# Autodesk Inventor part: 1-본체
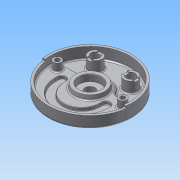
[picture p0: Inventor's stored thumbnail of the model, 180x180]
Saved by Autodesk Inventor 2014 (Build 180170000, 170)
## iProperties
Created: 2015-06
Part Number: 1-본체
Material: 알루미늄 6061
Document SubType Name: Modeling
Designer: Administrator
Density: 2.71 g/cm^3
Appearance: 알루미늄 - 평지
Mass: 1074.13 g
Surface Area: 1042.86 cm^2
Volume: 396.358 cm^3
Author: Administrator
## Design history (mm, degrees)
sketch "스케치1"
  geometry: C1 r 95 at (0, 0); 1 further point
  constraints: 1 centre point, 1 coincident
  dimensions: "d0" = 190 diameter of C1
extrude "돌출1" new body sketch "스케치1" distance "d1" = 32; taper "d2" = 0 deg
feature "쉘1" dims "d3" = 14, "d4" = 5
sketch "스케치2"
  geometry: L1 (0, 0)-(-94.075, -13.221); L2 (0, 0)-(94.075, -13.221); C1 r 90 at (0, 0) reference; A1 r 95 centre (0, 0) between (-94.075, -13.221) and (94.075, -13.221); 1 further point
  constraints: 4 end point, 3 point on circle, 1 centre point, 1 coincident, 1 vertical alignment, 2 other
  dimensions: "d5" = 164 deg angle of L2 L1
extrude "돌출2" cut sketch "스케치2" distance "d6" = 5; taper "d7" = 0 deg
sketch "스케치3"
  geometry: C1 r 90 at (0, 0) reference; C2 r 35 at (0, 0)
  constraints: 1 centre point, 1 coincident
  dimensions: "d8" = 70 diameter of C2
extrude "돌출3" join sketch "스케치3" distance "d9" = 10; taper "d10" = -10 deg
sketch "스케치4"
  geometry: C1 r 95 at (0, 0) reference; C2 r 26 at (0, 0)
  constraints: 1 centre point, 1 coincident
  dimensions: "d11" = 52 diameter of C2
extrude "돌출4" join sketch "스케치4" distance "d12" = 12; taper "d13" = -15 deg
hole "구멍1" diameter "d16" = 23; stored, may be unused: countersink angle "d20" = 90 deg, drill point angle "d22" = 118 deg; dims "d14" = 10, "d15" = 10, "d17" = 6, "d18" = 50, "d19" = 15, "d21" = 8
sketch "스케치5"
  geometry: L1 (-75.657, 16)-(-45.033, 16); L2 (45.033, 16)-(75.657, 16); C1 r 35 at (0, 0) reference; A1 r 90 centre (0, 0) between (-88.566, 16) and (88.566, 16) reference; A2 r 42 centre (0, 0) between (36.373, 21) and (-36.373, 21); A3 r 10 centre (-45.033, 26) between (-45.033, 16) and (-36.373, 21); A4 r 10 centre (45.033, 26) between (36.373, 21) and (45.033, 16); A5 r 90 centre (0, 0) between (85.114, 29.25) and (-85.114, 29.25); A6 r 10 centre (-75.657, 26) between (-85.114, 29.25) and (-75.657, 16); A7 r 10 centre (75.657, 26) between (75.657, 16) and (85.114, 29.25); 2 further points
  constraints: 19 point on circle, 8 tangent, 6 centre point, 4 end point, 4 point on line, 2 coincident, 2 equal radius, 2 horizontal, 1 collinear
  dimensions: "d23" = 42 radius of A2; "d24" = 16 distance from line of C1.centre L1; "d63" = 10 radius of A3; "d64" = 10 radius of A6
extrude "돌출5" cut sketch "스케치5" distance "d25" = 7; taper "d26" = 0 deg
sketch "스케치6"
  geometry: C1 r 15 at (-40, 52); C2 r 15 at (40, 52); A1 r 42 centre (0, 0) between (36.373, 21) and (-36.373, 21) reference; 2 further points
  constraints: 2 centre point, 1 equal radius, 1 horizontal alignment
  dimensions: "d27" = 80 distance of C2.centre C1.centre; "d28" = 52 vertical distance of A1.centre C1.centre; "d29" = 40 horizontal distance of A1.centre C1.centre; "d30" = 30 diameter of C1
extrude "돌출6" join sketch "스케치6" stored distance "d31" = 12; taper "d32" = 0 deg
sketch "스케치7"
  geometry: C1 r 15 at (0, 0) reference; C2 r 15 at (80, 0) reference; C3 r 10 at (0, 0); C4 r 10 at (80, 0); 1 further point
  constraints: 2 centre point, 2 coincident, 1 equal radius
  dimensions: "d33" = 20 diameter of C3
extrude "돌출7" cut sketch "스케치7" stored distance "d34" = 12; taper "d35" = 0 deg
sketch "스케치8"
  geometry: C1 r 9 at (-74, 0); C2 r 9 at (74, 0); A1 r 90 centre (0, 0) between (-85.114, 29.25) and (85.114, 29.25) reference; 2 further points
  constraints: 2 centre point, 2 horizontal alignment, 1 equal radius
  dimensions: "d36" = 148 distance of C2.centre C1.centre; "d37" = 74 distance of A1.centre C1.centre; "d38" = 18 diameter of C1
extrude "돌출8" join sketch "스케치8" stored distance "d39" = 12; taper "d40" = 0 deg
sketch "스케치9"
  geometry: L1 (75.657, 16)-(45.033, 16) reference; L2 (-59, -14)-(-59, -19); L3 (-41, -14)-(-41, -19); L4 (41, -14)-(41, -19); L5 (59, -14)-(59, -19); A1 r 90 centre (0, 0) between (-85.114, 29.25) and (85.114, 29.25) reference; A2 r 59 centre (0, -19) between (-59, -19) and (59, -19); A3 r 41 centre (0, -19) between (-41, -19) and (41, -19); A4 r 9 centre (-50, -14) between (-59, -14) and (-41, -14); A5 r 9 centre (50, -14) between (41, -14) and (59, -14); 3 further points
  constraints: 12 point on circle, 8 end point, 6 tangent, 4 centre point, 3 horizontal alignment, 3 parallel, 1 equal radius, 1 perpendicular, 1 vertical alignment
  dimensions: "d41" = 59 radius of A2; "d42" = 19 distance of A2.centre A1.centre; "d43" = 41 radius of A3; "d44" = 18 diameter of A4; "d45" = 5 vertical distance of A2.end A5.centre
extrude "돌출9" cut sketch "스케치9" distance "d46" = 7; taper "d47" = 0 deg
sketch "스케치10"
  geometry: L1 (-6, 13.748)-(-6, -13.748); L2 (6, 13.748)-(6, -13.748); L3 (66.252, 6)-(93.748, 6); L4 (66.252, -6)-(93.748, -6); A1 r 15 centre (0, 0) between (-6, 13.748) and (-6, -13.748) reference; A2 r 15 centre (80, 0) between (66.252, 6) and (93.748, 6) reference; 1 further point
  constraints: 8 end point, 8 point on circle, 3 parallel, 1 perpendicular, 1 vertical
  dimensions: "d48" = 12 distance between parallel lines of L2 L1; "d49" = 12 distance between parallel lines of L4 L3
extrude "돌출10" cut sketch "스케치10" distance "d50" = 3; taper "d51" = 0 deg
sketch "스케치11"
  geometry: C1 r 9 at (74, 0) reference; C2 r 9 at (-74, 0) reference; 2 further points
  constraints: 2 coincident
hole "구멍2" sketch "스케치11" at (-74, 0), (74, 0) diameter "d52" = 11; stored, may be unused: countersink angle "d56" = 90 deg, drill point angle "d58" = 118 deg; dims "d53" = 6, "d54" = 18, "d55" = 11, "d57" = 8
sketch "스케치12"
  geometry: C1 r 26 at (0, 0) reference; C2 r 95 at (0, 0) reference; A1 r 68 centre (0, 0) between (-68, 0) and (68, 0)
  constraints: 2 horizontal alignment, 2 point on circle, 1 centre point, 1 coincident, 1 other
  dimensions: "d60" = 68 radius of A1
feature "엠보싱1" sketch "스케치12" dims "d61" = 0.5, "d62" = 0
fillet "모깎기1" dims "d65" = 3, "d66" = 1, "d67" = 0.3, "d71" = 5
chamfer "모따기1" distance "d68" = 1; stored, may be unused: second distance "d69" = 2, angle "d70" = 45 deg
node "솔리드1"
